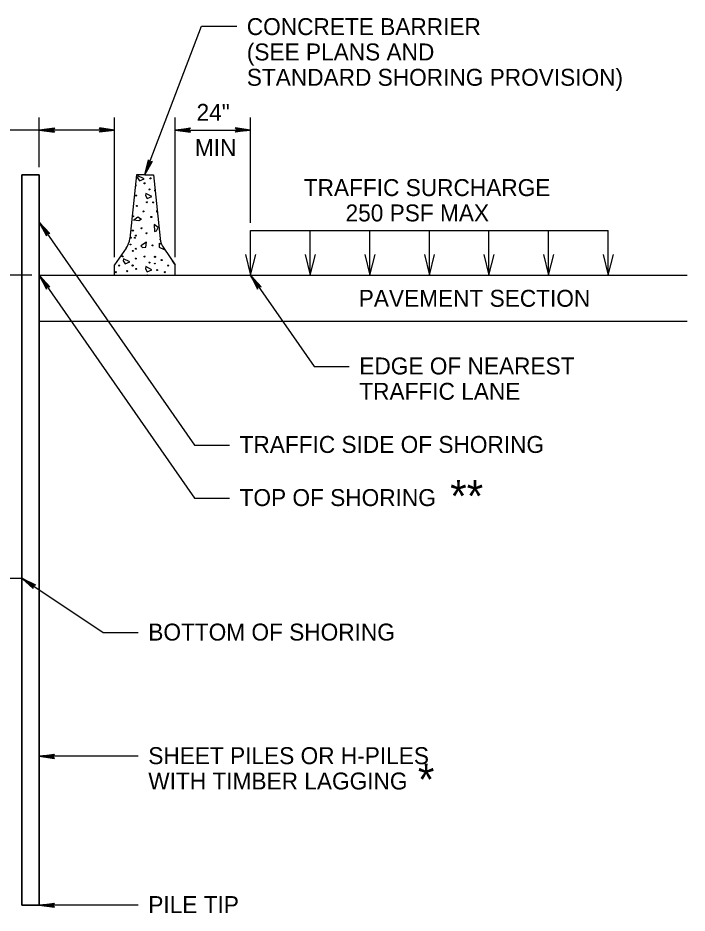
# Model space of a CAD drawing. Extents: x 1252282 to 1252638, y 733735 to 733845.
# Drawn here: x 1252507.94 to 1252534.73, y 733756.06 to 733791.87 of the extents above; entities that cross this region are included whole.
import ezdxf

# ---------------------------------------------------------------- set-up
doc = ezdxf.new("R2010")
doc.units = 0
doc.layers.add('Default', color=7, linetype='Continuous')

msp = doc.modelspace()

# ---------------------------------------------------------------- linework, layer by layer
at = {"layer": 'Default'}
for p, q in [((1252513.026, 733785.595), (1252515.292, 733791.547)), ((1252515.292, 733791.547), (1252516.7, 733791.547)), ((1252508.798, 733785.898), (1252508.798, 733787.894)), ((1252511.812, 733782.298), (1252511.812, 733787.894)), ((1252514.24, 733782.298), (1252514.24, 733787.894)), ((1252517.255, 733783.668), (1252517.255, 733787.894)), ((1252511.812, 733787.388), (1252492.328, 733787.388)), ((1252508.798, 733787.388), (1252509.411, 733787.472)), ((1252509.4, 733787.46), (1252508.798, 733787.388)), ((1252508.798, 733787.388), (1252509.388, 733787.448)), ((1252509.377, 733787.436), (1252508.798, 733787.388)), ((1252508.798, 733787.388), (1252509.365, 733787.424)), ((1252509.355, 733787.413), (1252508.798, 733787.388)), ((1252508.798, 733787.388), (1252509.343, 733787.401)), ((1252508.798, 733787.388), (1252509.411, 733787.306)), ((1252509.332, 733787.388), (1252508.798, 733787.388)), ((1252509.343, 733787.377), (1252508.798, 733787.388)), ((1252508.798, 733787.388), (1252509.355, 733787.365)), ((1252509.365, 733787.354), (1252508.798, 733787.388)), ((1252508.798, 733787.388), (1252509.377, 733787.341)), ((1252509.388, 733787.329), (1252508.798, 733787.388)), ((1252508.798, 733787.388), (1252509.4, 733787.318)), ((1252509.411, 733787.472), (1252509.332, 733787.388)), ((1252509.332, 733787.388), (1252509.411, 733787.306)), ((1252511.812, 733787.388), (1252511.2, 733787.471)), ((1252511.279, 733787.388), (1252511.2, 733787.471)), ((1252511.812, 733787.388), (1252511.2, 733787.305)), ((1252511.2, 733787.305), (1252511.279, 733787.388)), ((1252511.812, 733787.388), (1252511.211, 733787.459)), ((1252511.211, 733787.317), (1252511.812, 733787.388)), ((1252511.223, 733787.448), (1252511.812, 733787.388)), ((1252511.812, 733787.388), (1252511.223, 733787.329)), ((1252511.812, 733787.388), (1252511.234, 733787.436)), ((1252511.234, 733787.341), (1252511.812, 733787.388)), ((1252511.246, 733787.423), (1252511.812, 733787.388)), ((1252511.812, 733787.388), (1252511.246, 733787.353)), ((1252511.812, 733787.388), (1252511.256, 733787.412)), ((1252511.256, 733787.364), (1252511.812, 733787.388)), ((1252511.268, 733787.4), (1252511.812, 733787.388)), ((1252511.812, 733787.388), (1252511.268, 733787.376)), ((1252511.279, 733787.388), (1252511.812, 733787.388)), ((1252514.24, 733787.388), (1252514.853, 733787.471)), ((1252514.24, 733787.388), (1252514.842, 733787.459)), ((1252514.83, 733787.448), (1252514.24, 733787.388)), ((1252514.24, 733787.388), (1252514.819, 733787.436)), ((1252514.807, 733787.423), (1252514.24, 733787.388)), ((1252514.24, 733787.388), (1252514.797, 733787.412)), ((1252514.785, 733787.4), (1252514.24, 733787.388)), ((1252514.24, 733787.388), (1252514.853, 733787.305)), ((1252514.842, 733787.317), (1252514.24, 733787.388)), ((1252514.24, 733787.388), (1252514.83, 733787.329)), ((1252514.819, 733787.341), (1252514.24, 733787.388)), ((1252514.24, 733787.388), (1252514.807, 733787.353)), ((1252514.797, 733787.364), (1252514.24, 733787.388)), ((1252514.24, 733787.388), (1252514.785, 733787.376)), ((1252514.774, 733787.388), (1252514.24, 733787.388)), ((1252514.24, 733787.388), (1252517.255, 733787.388)), ((1252514.774, 733787.388), (1252514.853, 733787.471)), ((1252514.853, 733787.305), (1252514.774, 733787.388)), ((1252517.255, 733787.388), (1252516.642, 733787.472)), ((1252516.642, 733787.472), (1252516.721, 733787.388)), ((1252517.255, 733787.388), (1252516.642, 733787.306)), ((1252516.721, 733787.388), (1252516.642, 733787.306)), ((1252516.653, 733787.46), (1252517.255, 733787.388)), ((1252517.255, 733787.388), (1252516.653, 733787.318)), ((1252517.255, 733787.388), (1252516.665, 733787.448)), ((1252516.665, 733787.329), (1252517.255, 733787.388)), ((1252516.676, 733787.436), (1252517.255, 733787.388)), ((1252517.255, 733787.388), (1252516.676, 733787.341)), ((1252517.255, 733787.388), (1252516.688, 733787.424)), ((1252516.688, 733787.354), (1252517.255, 733787.388)), ((1252516.698, 733787.413), (1252517.255, 733787.388)), ((1252517.255, 733787.388), (1252516.698, 733787.365)), ((1252517.255, 733787.388), (1252516.71, 733787.401)), ((1252516.71, 733787.377), (1252517.255, 733787.388)), ((1252516.721, 733787.388), (1252517.255, 733787.388)), ((1252513.026, 733785.595), (1252513.166, 733786.197)), ((1252513.173, 733786.182), (1252513.026, 733785.595)), ((1252513.026, 733785.595), (1252513.18, 733786.167)), ((1252513.187, 733786.153), (1252513.026, 733785.595)), ((1252513.026, 733785.595), (1252513.321, 733786.138)), ((1252513.026, 733785.595), (1252513.195, 733786.137)), ((1252513.026, 733785.595), (1252513.306, 733786.132)), ((1252513.291, 733786.125), (1252513.026, 733785.595)), ((1252513.202, 733786.124), (1252513.026, 733785.595)), ((1252513.026, 733785.595), (1252513.276, 733786.119)), ((1252513.26, 733786.112), (1252513.026, 733785.595)), ((1252513.026, 733785.595), (1252513.208, 733786.108)), ((1252513.026, 733785.595), (1252513.246, 733786.107)), ((1252513.23, 733786.1), (1252513.026, 733785.595)), ((1252513.216, 733786.094), (1252513.026, 733785.595)), ((1252513.166, 733786.197), (1252513.216, 733786.094)), ((1252513.216, 733786.094), (1252513.321, 733786.138)), ((1252508.092, 733785.595), (1252508.798, 733785.595)), ((1252508.798, 733785.595), (1252508.092, 733785.595)), ((1252508.092, 733785.595), (1252508.092, 733769.461)), ((1252508.092, 733769.461), (1252508.092, 733785.595)), ((1252508.798, 733769.461), (1252508.798, 733785.595)), ((1252508.798, 733769.461), (1252508.798, 733785.595)), ((1252512.692, 733785.595), (1252512.421, 733783.047)), ((1252513.026, 733785.595), (1252512.692, 733785.595)), ((1252513.026, 733785.595), (1252513.361, 733785.595)), ((1252513.361, 733785.595), (1252513.632, 733783.047)), ((1252508.798, 733783.702), (1252509.215, 733783.246)), ((1252508.798, 733783.702), (1252509.079, 733783.152)), ((1252509.083, 733783.167), (1252508.798, 733783.702)), ((1252508.798, 733783.702), (1252509.086, 733783.184)), ((1252509.089, 733783.2), (1252508.798, 733783.702)), ((1252508.798, 733783.702), (1252509.093, 733783.217)), ((1252509.096, 733783.231), (1252508.798, 733783.702)), ((1252508.798, 733783.702), (1252509.099, 733783.248)), ((1252509.103, 733783.264), (1252508.798, 733783.702)), ((1252509.118, 733783.261), (1252508.798, 733783.702)), ((1252508.798, 733783.702), (1252509.135, 733783.258)), ((1252509.15, 733783.257), (1252508.798, 733783.702)), ((1252508.798, 733783.702), (1252509.167, 733783.254)), ((1252509.183, 733783.252), (1252508.798, 733783.702)), ((1252508.798, 733783.702), (1252509.199, 733783.248)), ((1252508.798, 733783.702), (1252515.003, 733774.785)), ((1252509.079, 733783.152), (1252509.103, 733783.264)), ((1252509.103, 733783.264), (1252509.215, 733783.246)), ((1252517.255, 733783.365), (1252531.565, 733783.365)), ((1252517.255, 733781.576), (1252517.255, 733783.365)), ((1252519.64, 733781.576), (1252519.64, 733783.365)), ((1252522.025, 733781.576), (1252522.025, 733783.365)), ((1252524.41, 733781.576), (1252524.41, 733783.365)), ((1252526.795, 733781.576), (1252526.795, 733783.365)), ((1252529.18, 733781.576), (1252529.18, 733783.365)), ((1252531.565, 733781.576), (1252531.565, 733783.365)), ((1252513.603, 733782.687), (1252513.612, 733782.858)), ((1252513.806, 733782.598), (1252513.603, 733782.687)), ((1252513.612, 733782.858), (1252513.688, 733782.821)), ((1252512.275, 733782.655), (1252511.812, 733781.995)), ((1252513.778, 733782.655), (1252514.24, 733781.995)), ((1252513.789, 733782.64), (1252513.806, 733782.598)), ((1252511.812, 733781.576), (1252511.812, 733781.995)), ((1252514.118, 733782.17), (1252514.114, 733782.15)), ((1252514.114, 733782.15), (1252514.191, 733782.031)), ((1252514.191, 733782.031), (1252514.209, 733782.039)), ((1252514.24, 733781.576), (1252514.24, 733781.995)), ((1252508.496, 733781.576), (1252504.594, 733781.576)), ((1252508.798, 733781.576), (1252515.003, 733772.659)), ((1252508.798, 733781.576), (1252509.215, 733781.12)), ((1252508.798, 733781.576), (1252509.079, 733781.026)), ((1252509.083, 733781.042), (1252508.798, 733781.576)), ((1252508.798, 733781.576), (1252509.086, 733781.058)), ((1252509.089, 733781.074), (1252508.798, 733781.576)), ((1252508.798, 733781.576), (1252509.093, 733781.091)), ((1252509.096, 733781.106), (1252508.798, 733781.576)), ((1252508.798, 733781.576), (1252509.099, 733781.122)), ((1252509.103, 733781.138), (1252508.798, 733781.576)), ((1252509.118, 733781.136), (1252508.798, 733781.576)), ((1252508.798, 733781.576), (1252509.135, 733781.133)), ((1252509.15, 733781.131), (1252508.798, 733781.576)), ((1252508.798, 733781.576), (1252509.167, 733781.128)), ((1252509.183, 733781.126), (1252508.798, 733781.576)), ((1252508.798, 733781.576), (1252509.199, 733781.123)), ((1252508.798, 733781.576), (1252534.725, 733781.576)), ((1252511.812, 733781.576), (1252514.24, 733781.576)), ((1252517.255, 733781.576), (1252517.671, 733781.12)), ((1252517.255, 733781.576), (1252517.536, 733781.026)), ((1252517.539, 733781.042), (1252517.255, 733781.576)), ((1252517.255, 733781.576), (1252517.542, 733781.058)), ((1252517.545, 733781.074), (1252517.255, 733781.576)), ((1252517.255, 733781.576), (1252517.549, 733781.091)), ((1252517.552, 733781.106), (1252517.255, 733781.576)), ((1252517.255, 733781.576), (1252517.555, 733781.122)), ((1252517.559, 733781.138), (1252517.255, 733781.576)), ((1252517.574, 733781.136), (1252517.255, 733781.576)), ((1252517.255, 733781.576), (1252517.591, 733781.133)), ((1252517.606, 733781.131), (1252517.255, 733781.576)), ((1252517.255, 733781.576), (1252517.623, 733781.128)), ((1252517.639, 733781.126), (1252517.255, 733781.576)), ((1252517.255, 733781.576), (1252517.655, 733781.123)), ((1252517.255, 733781.576), (1252519.795, 733777.925)), ((1252509.079, 733781.026), (1252509.103, 733781.138)), ((1252509.103, 733781.138), (1252509.215, 733781.12)), ((1252517.536, 733781.026), (1252517.559, 733781.138)), ((1252517.559, 733781.138), (1252517.671, 733781.12)), ((1252508.798, 733779.735), (1252534.725, 733779.735)), ((1252519.795, 733777.925), (1252521.204, 733777.925)), ((1252515.003, 733774.785), (1252516.411, 733774.785)), ((1252515.003, 733772.659), (1252516.411, 733772.659)), ((1252488.655, 733769.461), (1252508.092, 733769.461)), ((1252508.092, 733756.376), (1252508.092, 733769.461)), ((1252508.092, 733769.461), (1252508.092, 733756.376)), ((1252508.092, 733769.461), (1252511.349, 733767.279)), ((1252508.092, 733769.461), (1252508.646, 733769.188)), ((1252508.092, 733769.461), (1252508.554, 733769.051)), ((1252508.552, 733769.067), (1252508.092, 733769.461)), ((1252508.092, 733769.461), (1252508.548, 733769.083)), ((1252508.546, 733769.099), (1252508.092, 733769.461)), ((1252508.092, 733769.461), (1252508.543, 733769.116)), ((1252508.54, 733769.131), (1252508.092, 733769.461)), ((1252508.092, 733769.461), (1252508.537, 733769.147)), ((1252508.535, 733769.164), (1252508.092, 733769.461)), ((1252508.55, 733769.167), (1252508.092, 733769.461)), ((1252508.092, 733769.461), (1252508.567, 733769.17)), ((1252508.582, 733769.174), (1252508.092, 733769.461)), ((1252508.092, 733769.461), (1252508.599, 733769.178)), ((1252508.614, 733769.182), (1252508.092, 733769.461)), ((1252508.092, 733769.461), (1252508.63, 733769.185)), ((1252508.798, 733756.376), (1252508.798, 733769.461)), ((1252508.798, 733756.376), (1252508.798, 733769.461)), ((1252508.535, 733769.164), (1252508.646, 733769.188)), ((1252508.554, 733769.051), (1252508.535, 733769.164)), ((1252511.349, 733767.279), (1252512.758, 733767.279)), ((1252508.798, 733762.334), (1252509.411, 733762.417)), ((1252508.798, 733762.334), (1252509.4, 733762.405)), ((1252509.388, 733762.394), (1252508.798, 733762.334)), ((1252508.798, 733762.334), (1252509.377, 733762.382)), ((1252509.365, 733762.369), (1252508.798, 733762.334)), ((1252508.798, 733762.334), (1252509.355, 733762.358)), ((1252509.343, 733762.346), (1252508.798, 733762.334)), ((1252508.798, 733762.334), (1252509.411, 733762.251)), ((1252509.4, 733762.263), (1252508.798, 733762.334)), ((1252508.798, 733762.334), (1252509.388, 733762.275)), ((1252509.377, 733762.287), (1252508.798, 733762.334)), ((1252508.798, 733762.334), (1252509.365, 733762.299)), ((1252509.355, 733762.31), (1252508.798, 733762.334)), ((1252508.798, 733762.334), (1252509.343, 733762.322)), ((1252509.332, 733762.334), (1252508.798, 733762.334)), ((1252512.758, 733762.334), (1252508.798, 733762.334)), ((1252509.332, 733762.334), (1252509.411, 733762.417)), ((1252509.411, 733762.251), (1252509.332, 733762.334)), ((1252508.092, 733756.376), (1252508.798, 733756.376)), ((1252508.092, 733756.376), (1252508.798, 733756.376)), ((1252508.798, 733756.376), (1252509.411, 733756.458)), ((1252508.798, 733756.376), (1252509.4, 733756.446)), ((1252509.388, 733756.435), (1252508.798, 733756.376)), ((1252508.798, 733756.376), (1252509.377, 733756.423)), ((1252509.365, 733756.411), (1252508.798, 733756.376)), ((1252508.798, 733756.376), (1252509.355, 733756.399)), ((1252509.343, 733756.387), (1252508.798, 733756.376)), ((1252508.798, 733756.376), (1252509.411, 733756.293)), ((1252509.4, 733756.304), (1252508.798, 733756.376)), ((1252508.798, 733756.376), (1252509.388, 733756.316)), ((1252509.377, 733756.328), (1252508.798, 733756.376)), ((1252508.798, 733756.376), (1252509.365, 733756.341)), ((1252509.355, 733756.352), (1252508.798, 733756.376)), ((1252508.798, 733756.376), (1252509.343, 733756.363)), ((1252509.332, 733756.376), (1252508.798, 733756.376)), ((1252512.758, 733756.376), (1252508.798, 733756.376)), ((1252509.332, 733756.376), (1252509.411, 733756.458)), ((1252509.411, 733756.293), (1252509.332, 733756.376))]:
    msp.add_line(p, q, dxfattribs=at)
for points in [[(1252508.092, 733785.595), (1252508.798, 733785.595), (1252508.798, 733756.376), (1252508.092, 733756.376)], [(1252512.807, 733785.348), (1252512.99, 733785.432), (1252512.747, 733785.556), (1252512.73, 733785.468)], [(1252513.12, 733784.646), (1252513.303, 733784.73), (1252513.06, 733784.854), (1252513.044, 733784.766)], [(1252512.787, 733783.749), (1252512.569, 733783.781), (1252512.746, 733783.913), (1252512.89, 733783.82)], [(1252513.553, 733783.486), (1252513.39, 733783.603), (1252513.404, 733783.331), (1252513.488, 733783.36)], [(1252513.066, 733782.697), (1252513.086, 733782.897), (1252512.856, 733782.748), (1252512.925, 733782.69)], [(1252512.232, 733782.031), (1252512.416, 733782.115), (1252512.173, 733782.238), (1252512.155, 733782.15)], [(1252513.12, 733781.716), (1252513.303, 733781.8), (1252513.06, 733781.923), (1252513.044, 733781.835)]]:
    msp.add_lwpolyline(points, close=True, dxfattribs=at)
for points in [[(1252517.052, 733782.412), (1252517.255, 733781.576), (1252517.466, 733782.412)], [(1252519.438, 733782.412), (1252519.64, 733781.576), (1252519.851, 733782.412)], [(1252521.823, 733782.412), (1252522.025, 733781.576), (1252522.236, 733782.412)], [(1252524.208, 733782.412), (1252524.41, 733781.576), (1252524.621, 733782.412)], [(1252526.593, 733782.412), (1252526.795, 733781.576), (1252527.006, 733782.412)], [(1252528.978, 733782.412), (1252529.18, 733781.576), (1252529.391, 733782.412)], [(1252531.363, 733782.412), (1252531.565, 733781.576), (1252531.776, 733782.412)]]:
    msp.add_lwpolyline(points, dxfattribs=at)
for centre, radius in [((1252513.01, 733785.255), 0.0204), ((1252513.246, 733785.454), 0.0204), ((1252513.202, 733785.013), 0.0204), ((1252512.676, 733784.763), 0.0204), ((1252513.102, 733784.5), 0.0204), ((1252513.358, 733784.49), 0.0204), ((1252512.706, 733784.349), 0.0204), ((1252512.965, 733784.131), 0.0222), ((1252512.548, 733783.94), 0.0204), ((1252513.283, 733783.906), 0.022), ((1252512.889, 733783.458), 0.0204), ((1252512.456, 733783.078), 0.0204), ((1252512.541, 733783.361), 0.0217), ((1252512.623, 733783.077), 0.0204), ((1252512.665, 733783.167), 0.0204), ((1252513.088, 733783.258), 0.0204), ((1252512.448, 733782.806), 0.0137), ((1252513.328, 733782.769), 0.0204), ((1252512.131, 733782.334), 0.0204), ((1252512.539, 733782.549), 0.0204), ((1252512.665, 733782.636), 0.0204), ((1252513.01, 733782.325), 0.0204), ((1252513.427, 733782.314), 0.0204), ((1252511.994, 733781.965), 0.0222), ((1252512.532, 733781.969), 0.0217), ((1252512.656, 733782.244), 0.0204), ((1252513.202, 733782.083), 0.0204), ((1252513.419, 733782.042), 0.0137), ((1252513.694, 733782.182), 0.0204), ((1252513.953, 733781.965), 0.0222), ((1252511.863, 733781.701), 0.0204), ((1252512.312, 733781.74), 0.022), ((1252512.676, 733781.833), 0.0204), ((1252513.51, 733781.785), 0.0204), ((1252513.822, 733781.701), 0.0204)]:
    msp.add_circle(centre, radius, dxfattribs=at)
for centre, radius, start, end in [((1252512.656, 733785.174), 0.0204, 236.5303, 111.3602), ((1252513.419, 733784.972), 0.0137, 60.8328, 311.2767), ((1252513.504, 733784.136), 0.0217, 61.1718, 310.9377), ((1252511.589, 733783.135), 0.837, 325.0039, 353.9447), ((1252513.644, 733783.008), 0.0204, 120.119, 257.5399), ((1252514.464, 733783.135), 0.837, 186.0553, 214.9937), ((1252513.102, 733781.57), 0.0204, 17.8988, 162.1012)]:
    msp.add_arc(centre, radius, start, end, dxfattribs=at)

# ---------------------------------------------------------------- texts
for s, height, p in [('CONCRETE BARRIER', 0.67788, (1252517.102, 733791.185)), ('(SEE PLANS AND', 0.67788, (1252517.102, 733790.171)), ('STANDARD SHORING PROVISION)', 0.67788, (1252517.102, 733789.157)), ('24"', 0.6779, (1252515.091, 733787.755)), ('MIN', 0.6779, (1252515.022, 733786.344)), ('TRAFFIC SURCHARGE', 0.67788, (1252519.382, 733784.745)), ('250 PSF MAX', 0.67788, (1252521.055, 733783.731)), ('PAVEMENT SECTION', 0.67788, (1252521.582, 733780.316)), ('EDGE OF NEAREST', 0.67788, (1252521.605, 733777.609)), ('TRAFFIC LANE', 0.67788, (1252521.605, 733776.595)), ('TRAFFIC SIDE OF SHORING', 0.67788, (1252516.813, 733774.469)), ('**', 1.271, (1252525.242, 733772.11)), ('TOP OF SHORING', 0.67788, (1252516.813, 733772.344)), ('BOTTOM OF SHORING', 0.67788, (1252513.159, 733766.963)), ('SHEET PILES OR H-PILES', 0.67788, (1252513.159, 733762.019)), ('*', 1.271, (1252523.948, 733760.771)), ('WITH TIMBER LAGGING', 0.67788, (1252513.159, 733761.005)), ('PILE TIP', 0.6779, (1252513.159, 733756.06))]:
    msp.add_text(s, height=height, dxfattribs=at).set_placement(p)

doc.saveas('drawing.dxf')
